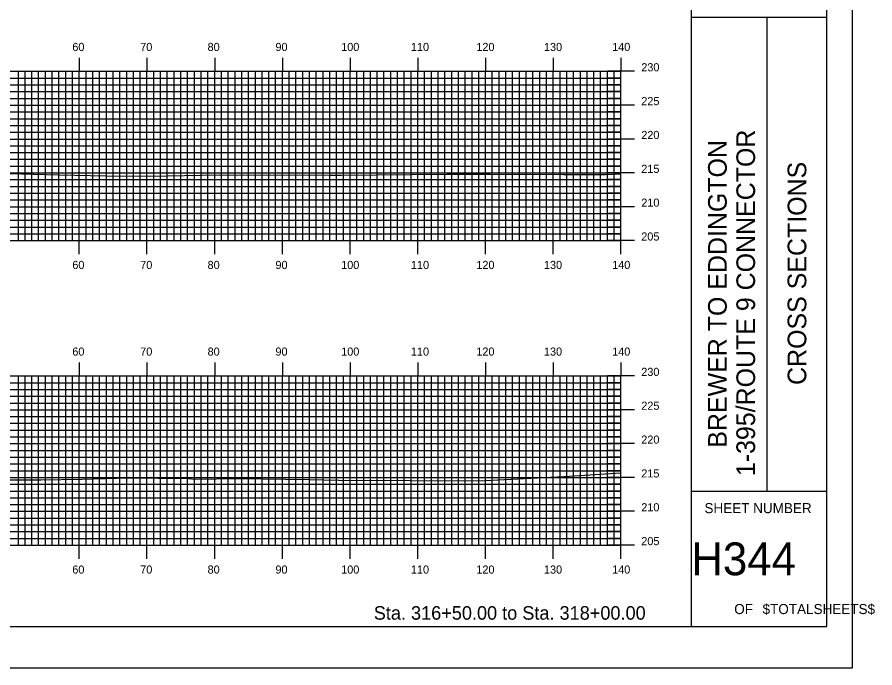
# Model space of a CAD drawing. Extents: x 1819637 to 1819981, y 442591 to 442811.
# Drawn here: x 1819854 to 1819980.7, y 442590.5 to 442686.7 of the extents above; entities that cross this region are included whole.
import ezdxf

# ---------------------------------------------------------------- set-up
doc = ezdxf.new("R2010")
doc.units = 0
for name, color, linetype in [('BORDER', 7, 'Continuous'), ('H_V ANNOTATION', 7, 'Continuous'), ('MAJOR', 7, 'Continuous'), ('MINOR', 7, 'Continuous'), ('PLOT BOUNDARY', 7, 'Continuous'), ('S_Roadway_Centerline', 7, 'Continuous')]:
    doc.layers.add(name, color=color, linetype=linetype)

msp = doc.modelspace()

# ---------------------------------------------------------------- linework, layer by layer
at = {"layer": 'BORDER'}
for p, q in [((1819953.58, 442596.67), (1819953.58, 442806.67)), ((1819953.58, 442686.67), (1819973.58, 442686.67)), ((1819964.76, 442616.67), (1819964.76, 442686.67)), ((1819953.58, 442616.67), (1819973.58, 442616.67))]:
    msp.add_line(p, q, dxfattribs=at)
msp.add_lwpolyline([(1819653.58, 442596.67), (1819973.58, 442596.67), (1819973.58, 442806.67), (1819653.58, 442806.67)], close=True, dxfattribs=at)
at = {"layer": 'MAJOR'}
for p, q in [((1819863.18, 442680.67), (1819863.18, 442678.67)), ((1819873.18, 442680.67), (1819873.18, 442678.67)), ((1819883.18, 442680.67), (1819883.18, 442678.67)), ((1819893.18, 442680.67), (1819893.18, 442678.67)), ((1819903.18, 442680.67), (1819903.18, 442678.67)), ((1819913.18, 442680.67), (1819913.18, 442678.67)), ((1819923.18, 442680.67), (1819923.18, 442678.67)), ((1819933.18, 442680.67), (1819933.18, 442678.67)), ((1819943.18, 442680.67), (1819943.18, 442678.67)), ((1819663.18, 442678.67), (1819943.18, 442678.67)), ((1819663.18, 442678.67), (1819943.18, 442678.67)), ((1819863.18, 442653.67), (1819863.18, 442678.67)), ((1819873.18, 442653.67), (1819873.18, 442678.67)), ((1819883.18, 442653.67), (1819883.18, 442678.67)), ((1819893.18, 442653.67), (1819893.18, 442678.67)), ((1819903.18, 442653.67), (1819903.18, 442678.67)), ((1819913.18, 442653.67), (1819913.18, 442678.67)), ((1819923.18, 442653.67), (1819923.18, 442678.67)), ((1819933.18, 442653.67), (1819933.18, 442678.67)), ((1819945.18, 442678.67), (1819941.17, 442678.67)), ((1819943.18, 442653.67), (1819943.18, 442678.67)), ((1819943.18, 442653.67), (1819943.18, 442678.67)), ((1819663.18, 442673.67), (1819943.18, 442673.67)), ((1819945.18, 442673.67), (1819941.17, 442673.67)), ((1819663.18, 442668.67), (1819943.18, 442668.67)), ((1819945.18, 442668.67), (1819941.17, 442668.67)), ((1819663.18, 442663.67), (1819943.18, 442663.67)), ((1819945.18, 442663.67), (1819941.17, 442663.67)), ((1819663.18, 442658.67), (1819943.18, 442658.67)), ((1819945.18, 442658.67), (1819941.17, 442658.67)), ((1819663.18, 442653.67), (1819943.18, 442653.67)), ((1819663.18, 442653.67), (1819943.18, 442653.67)), ((1819863.18, 442651.66), (1819863.18, 442653.67)), ((1819873.18, 442651.66), (1819873.18, 442653.67)), ((1819883.18, 442651.66), (1819883.18, 442653.67)), ((1819893.18, 442651.66), (1819893.18, 442653.67)), ((1819903.18, 442651.66), (1819903.18, 442653.67)), ((1819913.18, 442651.66), (1819913.18, 442653.67)), ((1819923.18, 442651.66), (1819923.18, 442653.67)), ((1819933.18, 442651.66), (1819933.18, 442653.67)), ((1819945.18, 442653.67), (1819941.17, 442653.67)), ((1819943.18, 442651.66), (1819943.18, 442653.67)), ((1819863.18, 442635.67), (1819863.18, 442633.67)), ((1819873.18, 442635.67), (1819873.18, 442633.67)), ((1819883.18, 442635.67), (1819883.18, 442633.67)), ((1819893.18, 442635.67), (1819893.18, 442633.67)), ((1819903.18, 442635.67), (1819903.18, 442633.67)), ((1819913.18, 442635.67), (1819913.18, 442633.67)), ((1819923.18, 442635.67), (1819923.18, 442633.67)), ((1819933.18, 442635.67), (1819933.18, 442633.67)), ((1819943.18, 442635.67), (1819943.18, 442633.67)), ((1819663.18, 442633.67), (1819943.18, 442633.67)), ((1819663.18, 442633.67), (1819943.18, 442633.67)), ((1819863.18, 442608.67), (1819863.18, 442633.67)), ((1819873.18, 442608.67), (1819873.18, 442633.67)), ((1819883.18, 442608.67), (1819883.18, 442633.67)), ((1819893.18, 442608.67), (1819893.18, 442633.67)), ((1819903.18, 442608.67), (1819903.18, 442633.67)), ((1819913.18, 442608.67), (1819913.18, 442633.67)), ((1819923.18, 442608.67), (1819923.18, 442633.67)), ((1819933.18, 442608.67), (1819933.18, 442633.67)), ((1819945.18, 442633.67), (1819941.17, 442633.67)), ((1819943.18, 442608.67), (1819943.18, 442633.67)), ((1819943.18, 442608.67), (1819943.18, 442633.67)), ((1819663.18, 442628.67), (1819943.18, 442628.67)), ((1819945.18, 442628.67), (1819941.17, 442628.67)), ((1819663.18, 442623.67), (1819943.18, 442623.67)), ((1819945.18, 442623.67), (1819941.17, 442623.67)), ((1819663.18, 442618.67), (1819943.18, 442618.67)), ((1819945.18, 442618.67), (1819941.17, 442618.67)), ((1819663.18, 442613.67), (1819943.18, 442613.67)), ((1819945.18, 442613.67), (1819941.17, 442613.67)), ((1819663.18, 442608.67), (1819943.18, 442608.67)), ((1819663.18, 442608.67), (1819943.18, 442608.67)), ((1819863.18, 442606.66), (1819863.18, 442608.67)), ((1819873.18, 442606.66), (1819873.18, 442608.67)), ((1819883.18, 442606.66), (1819883.18, 442608.67)), ((1819893.18, 442606.66), (1819893.18, 442608.67)), ((1819903.18, 442606.66), (1819903.18, 442608.67)), ((1819913.18, 442606.66), (1819913.18, 442608.67)), ((1819923.18, 442606.66), (1819923.18, 442608.67)), ((1819933.18, 442606.66), (1819933.18, 442608.67)), ((1819945.18, 442608.67), (1819941.17, 442608.67)), ((1819943.18, 442606.66), (1819943.18, 442608.67))]:
    msp.add_line(p, q, dxfattribs=at)
at = {"layer": 'MINOR'}
for p, q in [((1819854.18, 442653.67), (1819854.18, 442678.67)), ((1819855.18, 442653.67), (1819855.18, 442678.67)), ((1819856.18, 442653.67), (1819856.18, 442678.67)), ((1819857.18, 442653.67), (1819857.18, 442678.67)), ((1819858.18, 442653.67), (1819858.18, 442678.67)), ((1819859.18, 442653.67), (1819859.18, 442678.67)), ((1819860.18, 442653.67), (1819860.18, 442678.67)), ((1819861.18, 442653.67), (1819861.18, 442678.67)), ((1819862.18, 442653.67), (1819862.18, 442678.67)), ((1819864.18, 442653.67), (1819864.18, 442678.67)), ((1819865.18, 442653.67), (1819865.18, 442678.67)), ((1819866.18, 442653.67), (1819866.18, 442678.67)), ((1819867.18, 442653.67), (1819867.18, 442678.67)), ((1819868.18, 442653.67), (1819868.18, 442678.67)), ((1819869.18, 442653.67), (1819869.18, 442678.67)), ((1819870.18, 442653.67), (1819870.18, 442678.67)), ((1819871.18, 442653.67), (1819871.18, 442678.67)), ((1819872.18, 442653.67), (1819872.18, 442678.67)), ((1819874.18, 442653.67), (1819874.18, 442678.67)), ((1819875.18, 442653.67), (1819875.18, 442678.67)), ((1819876.18, 442653.67), (1819876.18, 442678.67)), ((1819877.18, 442653.67), (1819877.18, 442678.67)), ((1819878.18, 442653.67), (1819878.18, 442678.67)), ((1819879.18, 442653.67), (1819879.18, 442678.67)), ((1819880.18, 442653.67), (1819880.18, 442678.67)), ((1819881.18, 442653.67), (1819881.18, 442678.67)), ((1819882.18, 442653.67), (1819882.18, 442678.67)), ((1819884.18, 442653.67), (1819884.18, 442678.67)), ((1819885.18, 442653.67), (1819885.18, 442678.67)), ((1819886.18, 442653.67), (1819886.18, 442678.67)), ((1819887.18, 442653.67), (1819887.18, 442678.67)), ((1819888.18, 442653.67), (1819888.18, 442678.67)), ((1819889.18, 442653.67), (1819889.18, 442678.67)), ((1819890.18, 442653.67), (1819890.18, 442678.67)), ((1819891.18, 442653.67), (1819891.18, 442678.67)), ((1819892.18, 442653.67), (1819892.18, 442678.67)), ((1819894.18, 442653.67), (1819894.18, 442678.67)), ((1819895.18, 442653.67), (1819895.18, 442678.67)), ((1819896.18, 442653.67), (1819896.18, 442678.67)), ((1819897.18, 442653.67), (1819897.18, 442678.67)), ((1819898.18, 442653.67), (1819898.18, 442678.67)), ((1819899.18, 442653.67), (1819899.18, 442678.67)), ((1819900.18, 442653.67), (1819900.18, 442678.67)), ((1819901.18, 442653.67), (1819901.18, 442678.67)), ((1819902.18, 442653.67), (1819902.18, 442678.67)), ((1819904.18, 442653.67), (1819904.18, 442678.67)), ((1819905.18, 442653.67), (1819905.18, 442678.67)), ((1819906.18, 442653.67), (1819906.18, 442678.67)), ((1819907.18, 442653.67), (1819907.18, 442678.67)), ((1819908.18, 442653.67), (1819908.18, 442678.67)), ((1819909.18, 442653.67), (1819909.18, 442678.67)), ((1819910.18, 442653.67), (1819910.18, 442678.67)), ((1819911.18, 442653.67), (1819911.18, 442678.67)), ((1819912.18, 442653.67), (1819912.18, 442678.67)), ((1819914.18, 442653.67), (1819914.18, 442678.67)), ((1819915.18, 442653.67), (1819915.18, 442678.67)), ((1819916.18, 442653.67), (1819916.18, 442678.67)), ((1819917.18, 442653.67), (1819917.18, 442678.67)), ((1819918.18, 442653.67), (1819918.18, 442678.67)), ((1819919.18, 442653.67), (1819919.18, 442678.67)), ((1819920.18, 442653.67), (1819920.18, 442678.67)), ((1819921.18, 442653.67), (1819921.18, 442678.67)), ((1819922.18, 442653.67), (1819922.18, 442678.67)), ((1819924.18, 442653.67), (1819924.18, 442678.67)), ((1819925.18, 442653.67), (1819925.18, 442678.67)), ((1819926.18, 442653.67), (1819926.18, 442678.67)), ((1819927.18, 442653.67), (1819927.18, 442678.67)), ((1819928.18, 442653.67), (1819928.18, 442678.67)), ((1819929.18, 442653.67), (1819929.18, 442678.67)), ((1819930.18, 442653.67), (1819930.18, 442678.67)), ((1819931.18, 442653.67), (1819931.18, 442678.67)), ((1819932.18, 442653.67), (1819932.18, 442678.67)), ((1819934.18, 442653.67), (1819934.18, 442678.67)), ((1819935.18, 442653.67), (1819935.18, 442678.67)), ((1819936.18, 442653.67), (1819936.18, 442678.67)), ((1819937.18, 442653.67), (1819937.18, 442678.67)), ((1819938.18, 442653.67), (1819938.18, 442678.67)), ((1819939.18, 442653.67), (1819939.18, 442678.67)), ((1819940.18, 442653.67), (1819940.18, 442678.67)), ((1819941.18, 442653.67), (1819941.18, 442678.67)), ((1819942.18, 442653.67), (1819942.18, 442678.67)), ((1819663.18, 442677.67), (1819943.18, 442677.67)), ((1819943.18, 442677.67), (1819941.17, 442677.67)), ((1819663.18, 442676.67), (1819943.18, 442676.67)), ((1819943.18, 442676.67), (1819941.17, 442676.67)), ((1819663.18, 442675.67), (1819943.18, 442675.67)), ((1819943.18, 442675.67), (1819941.17, 442675.67)), ((1819663.18, 442674.67), (1819943.18, 442674.67)), ((1819943.18, 442674.67), (1819941.17, 442674.67)), ((1819663.18, 442672.67), (1819943.18, 442672.67)), ((1819943.18, 442672.67), (1819941.17, 442672.67)), ((1819663.18, 442671.67), (1819943.18, 442671.67)), ((1819943.18, 442671.67), (1819941.17, 442671.67)), ((1819663.18, 442670.67), (1819943.18, 442670.67)), ((1819943.18, 442670.67), (1819941.17, 442670.67)), ((1819663.18, 442669.67), (1819943.18, 442669.67)), ((1819943.18, 442669.67), (1819941.17, 442669.67)), ((1819663.18, 442667.67), (1819943.18, 442667.67)), ((1819943.18, 442667.67), (1819941.17, 442667.67)), ((1819663.18, 442666.67), (1819943.18, 442666.67)), ((1819943.18, 442666.67), (1819941.17, 442666.67)), ((1819663.18, 442665.67), (1819943.18, 442665.67)), ((1819663.18, 442664.67), (1819943.18, 442664.67)), ((1819943.18, 442665.67), (1819941.17, 442665.67)), ((1819943.18, 442664.67), (1819941.17, 442664.67)), ((1819663.18, 442662.67), (1819943.18, 442662.67)), ((1819943.18, 442662.67), (1819941.17, 442662.67)), ((1819663.18, 442661.67), (1819943.18, 442661.67)), ((1819943.18, 442661.67), (1819941.17, 442661.67)), ((1819663.18, 442660.67), (1819943.18, 442660.67)), ((1819663.18, 442659.67), (1819943.18, 442659.67)), ((1819943.18, 442660.67), (1819941.17, 442660.67)), ((1819943.18, 442659.67), (1819941.17, 442659.67)), ((1819663.18, 442657.67), (1819943.18, 442657.67)), ((1819943.18, 442657.67), (1819941.17, 442657.67)), ((1819663.18, 442656.67), (1819943.18, 442656.67)), ((1819943.18, 442656.67), (1819941.17, 442656.67)), ((1819663.18, 442655.67), (1819943.18, 442655.67)), ((1819663.18, 442654.67), (1819943.18, 442654.67)), ((1819943.18, 442655.67), (1819941.17, 442655.67)), ((1819943.18, 442654.67), (1819941.17, 442654.67)), ((1819854.18, 442608.67), (1819854.18, 442633.67)), ((1819855.18, 442608.67), (1819855.18, 442633.67)), ((1819856.18, 442608.67), (1819856.18, 442633.67)), ((1819857.18, 442608.67), (1819857.18, 442633.67)), ((1819858.18, 442608.67), (1819858.18, 442633.67)), ((1819859.18, 442608.67), (1819859.18, 442633.67)), ((1819860.18, 442608.67), (1819860.18, 442633.67)), ((1819861.18, 442608.67), (1819861.18, 442633.67)), ((1819862.18, 442608.67), (1819862.18, 442633.67)), ((1819864.18, 442608.67), (1819864.18, 442633.67)), ((1819865.18, 442608.67), (1819865.18, 442633.67)), ((1819866.18, 442608.67), (1819866.18, 442633.67)), ((1819867.18, 442608.67), (1819867.18, 442633.67)), ((1819868.18, 442608.67), (1819868.18, 442633.67)), ((1819869.18, 442608.67), (1819869.18, 442633.67)), ((1819870.18, 442608.67), (1819870.18, 442633.67)), ((1819871.18, 442608.67), (1819871.18, 442633.67)), ((1819872.18, 442608.67), (1819872.18, 442633.67)), ((1819874.18, 442608.67), (1819874.18, 442633.67)), ((1819875.18, 442608.67), (1819875.18, 442633.67)), ((1819876.18, 442608.67), (1819876.18, 442633.67)), ((1819877.18, 442608.67), (1819877.18, 442633.67)), ((1819878.18, 442608.67), (1819878.18, 442633.67)), ((1819879.18, 442608.67), (1819879.18, 442633.67)), ((1819880.18, 442608.67), (1819880.18, 442633.67)), ((1819881.18, 442608.67), (1819881.18, 442633.67)), ((1819882.18, 442608.67), (1819882.18, 442633.67)), ((1819884.18, 442608.67), (1819884.18, 442633.67)), ((1819885.18, 442608.67), (1819885.18, 442633.67)), ((1819886.18, 442608.67), (1819886.18, 442633.67)), ((1819887.18, 442608.67), (1819887.18, 442633.67)), ((1819888.18, 442608.67), (1819888.18, 442633.67)), ((1819889.18, 442608.67), (1819889.18, 442633.67)), ((1819890.18, 442608.67), (1819890.18, 442633.67)), ((1819891.18, 442608.67), (1819891.18, 442633.67)), ((1819892.18, 442608.67), (1819892.18, 442633.67)), ((1819894.18, 442608.67), (1819894.18, 442633.67)), ((1819895.18, 442608.67), (1819895.18, 442633.67)), ((1819896.18, 442608.67), (1819896.18, 442633.67)), ((1819897.18, 442608.67), (1819897.18, 442633.67)), ((1819898.18, 442608.67), (1819898.18, 442633.67)), ((1819899.18, 442608.67), (1819899.18, 442633.67)), ((1819900.18, 442608.67), (1819900.18, 442633.67)), ((1819901.18, 442608.67), (1819901.18, 442633.67)), ((1819902.18, 442608.67), (1819902.18, 442633.67)), ((1819904.18, 442608.67), (1819904.18, 442633.67)), ((1819905.18, 442608.67), (1819905.18, 442633.67)), ((1819906.18, 442608.67), (1819906.18, 442633.67)), ((1819907.18, 442608.67), (1819907.18, 442633.67)), ((1819908.18, 442608.67), (1819908.18, 442633.67)), ((1819909.18, 442608.67), (1819909.18, 442633.67)), ((1819910.18, 442608.67), (1819910.18, 442633.67)), ((1819911.18, 442608.67), (1819911.18, 442633.67)), ((1819912.18, 442608.67), (1819912.18, 442633.67)), ((1819914.18, 442608.67), (1819914.18, 442633.67)), ((1819915.18, 442608.67), (1819915.18, 442633.67)), ((1819916.18, 442608.67), (1819916.18, 442633.67)), ((1819917.18, 442608.67), (1819917.18, 442633.67)), ((1819918.18, 442608.67), (1819918.18, 442633.67)), ((1819919.18, 442608.67), (1819919.18, 442633.67)), ((1819920.18, 442608.67), (1819920.18, 442633.67)), ((1819921.18, 442608.67), (1819921.18, 442633.67)), ((1819922.18, 442608.67), (1819922.18, 442633.67)), ((1819924.18, 442608.67), (1819924.18, 442633.67)), ((1819925.18, 442608.67), (1819925.18, 442633.67)), ((1819926.18, 442608.67), (1819926.18, 442633.67)), ((1819927.18, 442608.67), (1819927.18, 442633.67)), ((1819928.18, 442608.67), (1819928.18, 442633.67)), ((1819929.18, 442608.67), (1819929.18, 442633.67)), ((1819930.18, 442608.67), (1819930.18, 442633.67)), ((1819931.18, 442608.67), (1819931.18, 442633.67)), ((1819932.18, 442608.67), (1819932.18, 442633.67)), ((1819934.18, 442608.67), (1819934.18, 442633.67)), ((1819935.18, 442608.67), (1819935.18, 442633.67)), ((1819936.18, 442608.67), (1819936.18, 442633.67)), ((1819937.18, 442608.67), (1819937.18, 442633.67)), ((1819938.18, 442608.67), (1819938.18, 442633.67)), ((1819939.18, 442608.67), (1819939.18, 442633.67)), ((1819940.18, 442608.67), (1819940.18, 442633.67)), ((1819941.18, 442608.67), (1819941.18, 442633.67)), ((1819942.18, 442608.67), (1819942.18, 442633.67)), ((1819663.18, 442632.67), (1819943.18, 442632.67)), ((1819943.18, 442632.67), (1819941.17, 442632.67)), ((1819663.18, 442631.67), (1819943.18, 442631.67)), ((1819663.18, 442630.67), (1819943.18, 442630.67)), ((1819943.18, 442631.67), (1819941.17, 442631.67)), ((1819943.18, 442630.67), (1819941.17, 442630.67)), ((1819663.18, 442629.67), (1819943.18, 442629.67)), ((1819943.18, 442629.67), (1819941.17, 442629.67)), ((1819663.18, 442627.67), (1819943.18, 442627.67)), ((1819663.18, 442626.67), (1819943.18, 442626.67)), ((1819943.18, 442627.67), (1819941.17, 442627.67)), ((1819943.18, 442626.67), (1819941.17, 442626.67)), ((1819663.18, 442625.67), (1819943.18, 442625.67)), ((1819943.18, 442625.67), (1819941.17, 442625.67)), ((1819663.18, 442624.67), (1819943.18, 442624.67)), ((1819943.18, 442624.67), (1819941.17, 442624.67)), ((1819663.18, 442622.67), (1819943.18, 442622.67)), ((1819663.18, 442621.67), (1819943.18, 442621.67)), ((1819943.18, 442622.67), (1819941.17, 442622.67)), ((1819943.18, 442621.67), (1819941.17, 442621.67)), ((1819663.18, 442620.67), (1819943.18, 442620.67)), ((1819943.18, 442620.67), (1819941.17, 442620.67)), ((1819663.18, 442619.67), (1819943.18, 442619.67)), ((1819943.18, 442619.67), (1819941.17, 442619.67)), ((1819663.18, 442617.67), (1819943.18, 442617.67)), ((1819663.18, 442616.67), (1819943.18, 442616.67)), ((1819943.18, 442617.67), (1819941.17, 442617.67)), ((1819943.18, 442616.67), (1819941.17, 442616.67)), ((1819663.18, 442615.67), (1819943.18, 442615.67)), ((1819943.18, 442615.67), (1819941.17, 442615.67)), ((1819663.18, 442614.67), (1819943.18, 442614.67)), ((1819943.18, 442614.67), (1819941.17, 442614.67)), ((1819663.18, 442612.67), (1819943.18, 442612.67)), ((1819663.18, 442611.67), (1819943.18, 442611.67)), ((1819943.18, 442612.67), (1819941.17, 442612.67)), ((1819943.18, 442611.67), (1819941.17, 442611.67)), ((1819663.18, 442610.67), (1819943.18, 442610.67)), ((1819943.18, 442610.67), (1819941.17, 442610.67)), ((1819663.18, 442609.67), (1819943.18, 442609.67)), ((1819943.18, 442609.67), (1819941.17, 442609.67))]:
    msp.add_line(p, q, dxfattribs=at)
at = {"layer": 'PLOT BOUNDARY'}
msp.add_lwpolyline([(1819637.39, 442590.55), (1819977.39, 442590.55), (1819977.39, 442810.55), (1819637.39, 442810.55)], close=True, dxfattribs=at)
at = {"layer": 'S_Roadway_Centerline'}
for points in [[(1819850.87, 442663.63), (1819860.19, 442663.38), (1819867.08, 442663.21), (1819873.51, 442663.19), (1819883.9, 442663.39), (1819900.26, 442663.31), (1819901.86, 442663.31), (1819917.5, 442663.49), (1819923.82, 442663.5), (1819934.67, 442663.44), (1819940.87, 442663.43), (1819943.18, 442663.55)], [(1819846.85, 442618.34), (1819857.51, 442618.33), (1819863.55, 442618.4), (1819870.51, 442618.63), (1819879.11, 442618.5), (1819880.34, 442618.4), (1819886.58, 442618.53), (1819897.14, 442618.35), (1819901.51, 442618.27), (1819912.09, 442618.2), (1819922.1, 442618.19), (1819934.74, 442618.83), (1819943.18, 442619.34)]]:
    msp.add_lwpolyline(points, dxfattribs=at)

# ---------------------------------------------------------------- texts
at = {"layer": 'BORDER'}
for s, p in [('1-395/ROUTE 9 CONNECTOR', (1819962.98, 442618.87)), ('BREWER TO EDDINGTON', (1819958.8, 442623.07)), ('CROSS SECTIONS', (1819970.55, 442632.34))]:
    msp.add_text(s, height=2.7557, rotation=90, dxfattribs=at).set_placement(p)
for s, height, p in [('SHEET NUMBER', 1.4905, (1819955.51, 442613.4)), ('H344', 4.839, (1819953.56, 442604.23)), ('$TOTALSHEETS$', 1.4905, (1819964.09, 442598.49)), ('OF', 1.491, (1819959.91, 442598.49))]:
    msp.add_text(s, height=height, dxfattribs=at).set_placement(p)
at = {"layer": 'H_V ANNOTATION'}
for s, height, p in [('60', 1.2, (1819862.15, 442681.67)), ('70', 1.2, (1819872.18, 442681.67)), ('80', 1.2, (1819882.13, 442681.67)), ('90', 1.2, (1819892.15, 442681.67)), ('100', 1.2, (1819901.86, 442681.67)), ('110', 1.2, (1819912.16, 442681.67)), ('120', 1.2, (1819921.82, 442681.67)), ('130', 1.2, (1819931.81, 442681.67)), ('140', 1.2, (1819941.88, 442681.67)), ('230', 1.2, (1819946.18, 442678.67)), ('225', 1.2, (1819946.18, 442673.67)), ('220', 1.2, (1819946.18, 442668.67)), ('215', 1.2, (1819946.18, 442663.67)), ('210', 1.2, (1819946.18, 442658.67)), ('205', 1.2, (1819946.18, 442653.67)), ('60', 1.2, (1819862.15, 442649.47)), ('70', 1.2, (1819872.18, 442649.47)), ('80', 1.2, (1819882.13, 442649.47)), ('90', 1.2, (1819892.15, 442649.47)), ('100', 1.2, (1819901.86, 442649.47)), ('110', 1.2, (1819912.16, 442649.47)), ('120', 1.2, (1819921.82, 442649.47)), ('130', 1.2, (1819931.81, 442649.47)), ('140', 1.2, (1819941.88, 442649.47)), ('60', 1.2, (1819862.15, 442636.67)), ('70', 1.2, (1819872.18, 442636.67)), ('80', 1.2, (1819882.13, 442636.67)), ('90', 1.2, (1819892.15, 442636.67)), ('100', 1.2, (1819901.86, 442636.67)), ('110', 1.2, (1819912.16, 442636.67)), ('120', 1.2, (1819921.82, 442636.67)), ('130', 1.2, (1819931.81, 442636.67)), ('140', 1.2, (1819941.88, 442636.67)), ('230', 1.2, (1819946.18, 442633.67)), ('225', 1.2, (1819946.18, 442628.67)), ('220', 1.2, (1819946.18, 442623.67)), ('215', 1.2, (1819946.18, 442618.67)), ('210', 1.2, (1819946.18, 442613.67)), ('205', 1.2, (1819946.18, 442608.67)), ('60', 1.2, (1819862.15, 442604.47)), ('70', 1.2, (1819872.18, 442604.47)), ('80', 1.2, (1819882.13, 442604.47)), ('90', 1.2, (1819892.15, 442604.47)), ('100', 1.2, (1819901.86, 442604.47)), ('110', 1.2, (1819912.16, 442604.47)), ('120', 1.2, (1819921.82, 442604.47)), ('130', 1.2, (1819931.81, 442604.47)), ('140', 1.2, (1819941.88, 442604.47)), ('Sta. 316+50.00 to Sta. 318+00.00', 2.0004, (1819906.67, 442597.66))]:
    msp.add_text(s, height=height, dxfattribs=at).set_placement(p)

doc.saveas('drawing.dxf')
